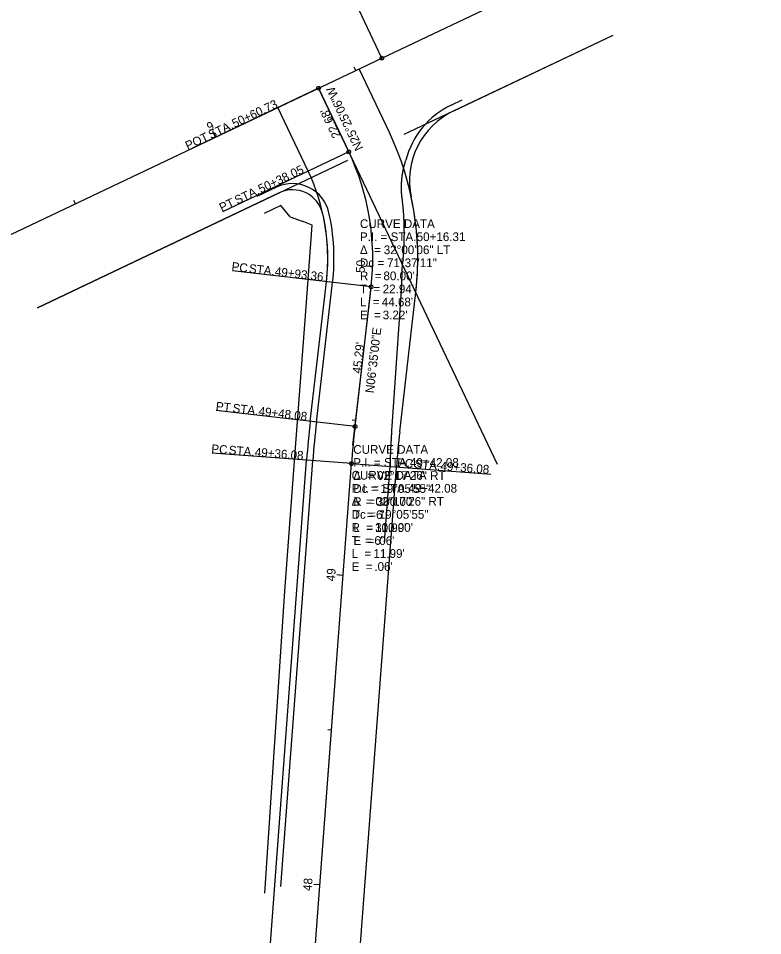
# Model space of a CAD drawing. Extents: x 219353 to 221640, y 361458 to 364236.
# Drawn here: x 220121.2 to 220361, y 361769.6 to 362065.1 of the extents above; entities that cross this region are included whole.
import ezdxf

# ---------------------------------------------------------------- set-up
doc = ezdxf.new("R2010")
doc.units = 0
for name, color, linetype in [('DR_P_Cells', 7, 'Continuous'), ('DR_P_GenericNode', 7, 'Continuous'), ('DR_P_Storm_Sewer', 7, 'Continuous'), ('DR_X_Cells', 7, 'Continuous'), ('DR_X_Storm_Sewer', 7, 'Continuous'), ('DT_X_Contour_Major', 7, 'Continuous'), ('DT_X_Contour_Minor', 7, 'Continuous'), ('SC_ProfileRun1', 7, 'Continuous'), ('SC_ProfileRun2', 7, 'Continuous'), ('SC_ProfileRun3', 7, 'Continuous'), ('SC_Scratch1', 7, 'Continuous'), ('UT_X_Sanitary_Cells', 7, 'Continuous'), ('UT_X_Sanitary_Line', 7, 'Continuous')]:
    doc.layers.add(name, color=color, linetype=linetype)

msp = doc.modelspace()

# ---------------------------------------------------------------- linework, layer by layer
at = {"layer": 'DR_X_Cells'}
for p, q in [((220238.34, 362052.3), (220219.02, 362092.94)), ((220217.91, 362042.59), (220177.27, 362023.28)), ((220227.64, 362022.11), (220187, 362002.79)), ((220234.86, 361978.6), (220190.16, 361983.76)), ((220229.67, 361933.61), (220184.97, 361938.77)), ((220228.53, 361921.67), (220273.41, 361918.3))]:
    msp.add_line(p, q, dxfattribs=at)
for centre in [(220238.34, 362052.3), (220217.91, 362042.59), (220227.64, 362022.11), (220234.86, 361978.6), (220229.67, 361933.61), (220228.53, 361921.67)]:
    msp.add_circle(centre, 0.6, dxfattribs=at)
at = {"layer": 'DT_X_Contour_Major'}
for p, q in [((220238.34, 362052.3), (220361, 362110.59)), ((220238.34, 362052.3), (220342.97, 362102.03)), ((220238.34, 362052.3), (220342.97, 362102.03)), ((219371.89, 361640.54), (220238.34, 362052.3)), ((219371.89, 361640.54), (220238.34, 362052.3)), ((220217.91, 362042.59), (220275.47, 361921.48)), ((220217.91, 362042.59), (220227.64, 362022.11)), ((220227.64, 362022.11), (220217.91, 362042.59)), ((220229.67, 361933.61), (220234.86, 361978.6)), ((220228.98, 361927.65), (220234.72, 361977.36)), ((220203.38, 361586.53), (220228.53, 361921.67)), ((220203.38, 361586.53), (220223.37, 361852.86))]:
    msp.add_line(p, q, dxfattribs=at)
for centre, radius, start, end in [((220155.39, 361987.77), 80, 353.4167, 25.4184), ((220155.39, 361987.77), 80, 353.4167, 25.4184), ((220527.69, 361899.21), 300, 173.4167, 175.7073), ((220527.69, 361899.21), 300, 173.4167, 175.7073)]:
    msp.add_arc(centre, radius, start, end, dxfattribs=at)
at = {"layer": 'DT_X_Contour_Minor'}
for p, q in [((220249.18, 362029.49), (220312.8, 362059.72)), ((220261.51, 362035.35), (220312.8, 362059.72)), ((220261.51, 362035.35), (220312.8, 362059.72)), ((220240.74, 362028.33), (220231.01, 362048.82)), ((220214.55, 362015.88), (220204.81, 362036.37)), ((220245.5, 362027.74), (220249.18, 362029.49)), ((220127.4, 361971.9), (220227.38, 362019.41)), ((220127.4, 361971.9), (220205.26, 362008.9)), ((220205.26, 362008.9), (220127.4, 361971.9)), ((220205.75, 362004.82), (220200.36, 362002.26)), ((220208.77, 362001.19), (220205.75, 362004.82)), ((220208.77, 362001.19), (220212.63, 361999.74)), ((220215.91, 361998.51), (220212.63, 361999.74)), ((220213.89, 361972.18), (220215.91, 361998.51)), ((220215.26, 361935.27), (220220.46, 361980.26)), ((220215.26, 361935.27), (220220.46, 361980.26)), ((220215.26, 361935.27), (220220.46, 361980.26)), ((220244.07, 361931.95), (220249.26, 361976.94)), ((220244.07, 361931.95), (220249.26, 361976.94)), ((220244.07, 361931.95), (220249.26, 361976.94)), ((220210.44, 361925.41), (220213.89, 361972.18)), ((220188.92, 361587.61), (220214.07, 361922.75)), ((220188.92, 361587.61), (220214.07, 361922.75)), ((220188.92, 361587.61), (220214.07, 361922.75)), ((220207.08, 361880.55), (220210.44, 361925.41)), ((220217.83, 361585.44), (220242.99, 361920.58)), ((220217.83, 361585.44), (220242.99, 361920.58)), ((220217.83, 361585.44), (220242.99, 361920.58)), ((220200.58, 361783.34), (220207.08, 361880.55))]:
    msp.add_line(p, q, dxfattribs=at)
for centre, radius, start, end in [((220272.24, 362012.77), 25, 115.4184, 192.0775), ((220272.24, 362012.77), 25, 115.4184, 192.0775), ((220155.39, 361987.77), 94.5, 353.4167, 25.4184), ((220155.39, 361987.77), 65.5, 353.4167, 25.4184), ((220209.55, 361999.87), 10, 12.5928, 115.4184), ((220209.55, 361999.87), 10, 12.5928, 115.4184), ((220155.39, 361987.77), 94.5, 353.4167, 12.0775), ((220155.39, 361987.77), 94.5, 353.4167, 12.0775), ((220155.39, 361987.77), 65.5, 353.4167, 12.5928), ((220155.39, 361987.77), 65.5, 353.4167, 12.5928), ((220527.69, 361899.21), 314.5, 173.4167, 175.7073), ((220527.69, 361899.21), 314.5, 173.4167, 175.7073), ((220527.69, 361899.21), 314.5, 173.4167, 175.7073), ((220527.69, 361899.21), 285.5, 173.4167, 175.7073), ((220527.69, 361899.21), 285.5, 173.4167, 175.7073), ((220527.69, 361899.21), 285.5, 173.4167, 175.7073)]:
    msp.add_arc(centre, radius, start, end, dxfattribs=at)
at = {"layer": 'SC_ProfileRun2'}
for p, q in [((220238.34, 362052.3), (220219.02, 362092.94)), ((220217.91, 362042.59), (220177.27, 362023.28)), ((220217.91, 362042.59), (220177.27, 362023.28)), ((220227.64, 362022.11), (220187, 362002.79)), ((220227.64, 362022.11), (220187, 362002.79)), ((220234.86, 361978.6), (220190.16, 361983.76)), ((220234.86, 361978.6), (220190.16, 361983.76)), ((220229.67, 361933.61), (220184.97, 361938.77)), ((220229.67, 361933.61), (220184.97, 361938.77)), ((220228.53, 361921.67), (220183.66, 361925.04)), ((220228.53, 361921.67), (220273.41, 361918.3))]:
    msp.add_line(p, q, dxfattribs=at)
for centre in [(220238.34, 362052.3), (220217.91, 362042.59), (220217.91, 362042.59), (220227.64, 362022.11), (220227.64, 362022.11), (220234.86, 361978.6), (220234.86, 361978.6), (220229.67, 361933.61), (220229.67, 361933.61), (220228.53, 361921.67), (220228.53, 361921.67)]:
    msp.add_circle(centre, 0.6, dxfattribs=at)
at = {"layer": 'SC_ProfileRun3'}
for p, q in [((220184.77, 362026.84), (220184.26, 362027.93)), ((220235.35, 361985.21), (220233.35, 361985.28)), ((220235.35, 361985.21), (220233.35, 361985.28)), ((220225.83, 361885.69), (220224.63, 361885.78)), ((220225.83, 361885.69), (220224.63, 361885.78)), ((220218.35, 361785.97), (220217.15, 361786.06)), ((220218.35, 361785.97), (220217.15, 361786.06))]:
    msp.add_line(p, q, dxfattribs=at)
at = {"layer": 'UT_X_Sanitary_Cells'}
for p, q in [((220229.93, 362048.31), (220229.42, 362049.39)), ((220222.51, 362032.9), (220221.43, 362032.39)), ((220184.77, 362026.84), (220183.91, 362028.65)), ((220139.61, 362005.38), (220139.1, 362006.47)), ((220235.35, 361985.21), (220233.35, 361985.28)), ((220229.89, 361935.52), (220228.7, 361935.66)), ((220225.83, 361885.69), (220223.84, 361885.84)), ((220222.09, 361835.83), (220220.89, 361835.92)), ((220218.35, 361785.97), (220216.35, 361786.12))]:
    msp.add_line(p, q, dxfattribs=at)
at = {"layer": 'UT_X_Sanitary_Line'}
for p, q in [((220260.65, 362037.16), (220264.17, 362038.83)), ((220260.65, 362037.16), (220264.17, 362038.83)), ((220260.65, 362037.16), (220264.17, 362038.83)), ((220204.4, 362010.71), (220198.04, 362007.68)), ((220217.25, 361935.04), (220222.44, 361980.03)), ((220241.57, 361932.23), (220244.64, 361977.47)), ((220241.57, 361932.23), (220244.64, 361977.47)), ((220241.57, 361932.23), (220244.64, 361977.47)), ((220205.77, 361785.49), (220216.07, 361922.6)), ((220239.17, 361896.41), (220241, 361920.73)), ((220239.17, 361896.41), (220241, 361920.73))]:
    msp.add_line(p, q, dxfattribs=at)
for centre, radius, start, end in [((220272.24, 362012.77), 27, 115.4184, 165.8654), ((220272.24, 362012.77), 27, 115.4184, 165.8654), ((220272.24, 362012.77), 27, 115.4184, 165.8654), ((220209.55, 361999.87), 12, 12.5928, 115.4184), ((220155.39, 361987.77), 67.5, 353.4167, 12.5928), ((220527.69, 361899.21), 312.5, 173.4167, 175.7073), ((220527.69, 361899.21), 287.5, 175.6312, 175.7073), ((220527.69, 361899.21), 287.5, 175.6312, 175.7073)]:
    msp.add_arc(centre, radius, start, end, dxfattribs=at)
for points in [[(220244.88, 362006.92), (220244.85, 362007.13), (220244.8, 362007.55), (220244.74, 362008.19), (220244.69, 362008.83), (220244.65, 362009.47), (220244.63, 362010.1), (220244.63, 362010.74), (220244.64, 362011.37), (220244.66, 362012.01), (220244.7, 362012.64), (220244.75, 362013.27), (220244.82, 362013.89), (220244.9, 362014.52), (220245, 362015.14), (220245.11, 362015.75), (220245.23, 362016.37), (220245.37, 362016.98), (220245.52, 362017.58), (220245.69, 362018.18), (220245.87, 362018.78), (220246, 362019.17), (220246.06, 362019.37)], [(220244.88, 362006.92), (220244.85, 362007.13), (220244.8, 362007.55), (220244.74, 362008.19), (220244.69, 362008.83), (220244.65, 362009.47), (220244.63, 362010.1), (220244.63, 362010.74), (220244.64, 362011.37), (220244.66, 362012.01), (220244.7, 362012.64), (220244.75, 362013.27), (220244.82, 362013.89), (220244.9, 362014.52), (220245, 362015.14), (220245.11, 362015.75), (220245.23, 362016.37), (220245.37, 362016.98), (220245.52, 362017.58), (220245.69, 362018.18), (220245.87, 362018.78), (220246, 362019.17), (220246.06, 362019.37)], [(220244.88, 362006.92), (220244.85, 362007.13), (220244.8, 362007.55), (220244.74, 362008.19), (220244.69, 362008.83), (220244.65, 362009.47), (220244.63, 362010.1), (220244.63, 362010.74), (220244.64, 362011.37), (220244.66, 362012.01), (220244.7, 362012.64), (220244.75, 362013.27), (220244.82, 362013.89), (220244.9, 362014.52), (220245, 362015.14), (220245.11, 362015.75), (220245.23, 362016.37), (220245.37, 362016.98), (220245.52, 362017.58), (220245.69, 362018.18), (220245.87, 362018.78), (220246, 362019.17), (220246.06, 362019.37)], [(220244.82, 361984.32), (220244.87, 361984.69), (220244.96, 361985.43), (220245.08, 361986.55), (220245.19, 361987.67), (220245.29, 361988.79), (220245.37, 361989.91), (220245.44, 361991.04), (220245.49, 361992.16), (220245.53, 361993.29), (220245.55, 361994.42), (220245.56, 361995.56), (220245.56, 361996.69), (220245.54, 361997.82), (220245.51, 361998.96), (220245.46, 362000.1), (220245.4, 362001.23), (220245.33, 362002.37), (220245.24, 362003.51), (220245.14, 362004.64), (220245.02, 362005.78), (220244.93, 362006.54), (220244.88, 362006.92)], [(220244.82, 361984.32), (220244.87, 361984.69), (220244.96, 361985.43), (220245.08, 361986.55), (220245.19, 361987.67), (220245.29, 361988.79), (220245.37, 361989.91), (220245.44, 361991.04), (220245.49, 361992.16), (220245.53, 361993.29), (220245.55, 361994.42), (220245.56, 361995.56), (220245.56, 361996.69), (220245.54, 361997.82), (220245.51, 361998.96), (220245.46, 362000.1), (220245.4, 362001.23), (220245.33, 362002.37), (220245.24, 362003.51), (220245.14, 362004.64), (220245.02, 362005.78), (220244.93, 362006.54), (220244.88, 362006.92)], [(220244.82, 361984.32), (220244.87, 361984.69), (220244.96, 361985.43), (220245.08, 361986.55), (220245.19, 361987.67), (220245.29, 361988.79), (220245.37, 361989.91), (220245.44, 361991.04), (220245.49, 361992.16), (220245.53, 361993.29), (220245.55, 361994.42), (220245.56, 361995.56), (220245.56, 361996.69), (220245.54, 361997.82), (220245.51, 361998.96), (220245.46, 362000.1), (220245.4, 362001.23), (220245.33, 362002.37), (220245.24, 362003.51), (220245.14, 362004.64), (220245.02, 362005.78), (220244.93, 362006.54), (220244.88, 362006.92)], [(220244.64, 361977.47), (220244.64, 361977.58), (220244.66, 361977.81), (220244.68, 361978.15), (220244.7, 361978.5), (220244.72, 361978.84), (220244.73, 361979.18), (220244.75, 361979.53), (220244.76, 361979.87), (220244.77, 361980.21), (220244.78, 361980.55), (220244.79, 361980.9), (220244.8, 361981.24), (220244.81, 361981.58), (220244.82, 361981.92), (220244.82, 361982.27), (220244.82, 361982.61), (220244.83, 361982.95), (220244.83, 361983.29), (220244.83, 361983.64), (220244.83, 361983.98), (220244.82, 361984.21), (220244.82, 361984.32)], [(220244.64, 361977.47), (220244.64, 361977.58), (220244.66, 361977.81), (220244.68, 361978.15), (220244.7, 361978.5), (220244.72, 361978.84), (220244.73, 361979.18), (220244.75, 361979.53), (220244.76, 361979.87), (220244.77, 361980.21), (220244.78, 361980.55), (220244.79, 361980.9), (220244.8, 361981.24), (220244.81, 361981.58), (220244.82, 361981.92), (220244.82, 361982.27), (220244.82, 361982.61), (220244.83, 361982.95), (220244.83, 361983.29), (220244.83, 361983.64), (220244.83, 361983.98), (220244.82, 361984.21), (220244.82, 361984.32)], [(220244.64, 361977.47), (220244.64, 361977.58), (220244.66, 361977.81), (220244.68, 361978.15), (220244.7, 361978.5), (220244.72, 361978.84), (220244.73, 361979.18), (220244.75, 361979.53), (220244.76, 361979.87), (220244.77, 361980.21), (220244.78, 361980.55), (220244.79, 361980.9), (220244.8, 361981.24), (220244.81, 361981.58), (220244.82, 361981.92), (220244.82, 361982.27), (220244.82, 361982.61), (220244.83, 361982.95), (220244.83, 361983.29), (220244.83, 361983.64), (220244.83, 361983.98), (220244.82, 361984.21), (220244.82, 361984.32)], [(220241.03, 361921.11), (220241.03, 361921.3), (220241.04, 361921.67), (220241.06, 361922.23), (220241.08, 361922.78), (220241.1, 361923.34), (220241.12, 361923.89), (220241.14, 361924.45), (220241.17, 361925.01), (220241.19, 361925.56), (220241.22, 361926.12), (220241.24, 361926.67), (220241.27, 361927.23), (220241.3, 361927.79), (220241.33, 361928.34), (220241.36, 361928.9), (220241.39, 361929.45), (220241.43, 361930.01), (220241.46, 361930.57), (220241.49, 361931.12), (220241.53, 361931.68), (220241.56, 361932.05), (220241.57, 361932.23)], [(220241.03, 361921.11), (220241.03, 361921.3), (220241.04, 361921.67), (220241.06, 361922.23), (220241.08, 361922.78), (220241.1, 361923.34), (220241.12, 361923.89), (220241.14, 361924.45), (220241.17, 361925.01), (220241.19, 361925.56), (220241.22, 361926.12), (220241.24, 361926.67), (220241.27, 361927.23), (220241.3, 361927.79), (220241.33, 361928.34), (220241.36, 361928.9), (220241.39, 361929.45), (220241.43, 361930.01), (220241.46, 361930.57), (220241.49, 361931.12), (220241.53, 361931.68), (220241.56, 361932.05), (220241.57, 361932.23)], [(220241.03, 361921.11), (220241.03, 361921.3), (220241.04, 361921.67), (220241.06, 361922.23), (220241.08, 361922.78), (220241.1, 361923.34), (220241.12, 361923.89), (220241.14, 361924.45), (220241.17, 361925.01), (220241.19, 361925.56), (220241.22, 361926.12), (220241.24, 361926.67), (220241.27, 361927.23), (220241.3, 361927.79), (220241.33, 361928.34), (220241.36, 361928.9), (220241.39, 361929.45), (220241.43, 361930.01), (220241.46, 361930.57), (220241.49, 361931.12), (220241.53, 361931.68), (220241.56, 361932.05), (220241.57, 361932.23)]]:
    msp.add_open_spline(points, degree=3, dxfattribs=at)

# ---------------------------------------------------------------- texts
at = {"layer": 'DR_P_Cells'}
for s, rotation, p in [("22.68'", 115.4184, (220225.13, 362027.31)), ("45.29'", 83.4167, (220231.59, 361950.58))]:
    msp.add_text(s, height=2.8, rotation=rotation, dxfattribs=at).set_placement(p)
at = {"layer": 'DR_P_GenericNode'}
for s, rotation, p in [("22.68'", 115.4184, (220225.13, 362027.31)), ("22.68'", 115.4184, (220225.13, 362027.31)), ("45.29'", 83.4167, (220231.59, 361950.58)), ("45.29'", 83.4167, (220231.59, 361950.58))]:
    msp.add_text(s, height=2.8, rotation=rotation, dxfattribs=at).set_placement(p)
at = {"layer": 'DR_P_Storm_Sewer'}
for s, p in [('CURVE DATA', (220231.25, 361997.55)), ('P.I. = STA. ', (220231.25, 361993.35)), ('50+16.31', (220249.52, 361993.35)), ('Δ  = ', (220231.25, 361989.15)), ('32°00\'06" LT', (220238.93, 361989.15)), ('Dc = ', (220231.25, 361984.95)), ('71°37\'11"', (220239.99, 361984.95)), ('R  = ', (220231.25, 361980.75)), ("80.00'", (220238.83, 361980.75)), ('T  = ', (220231.25, 361976.55)), ("22.94'", (220238.59, 361976.55)), ('L  = ', (220231.25, 361972.35)), ("44.68'", (220238.29, 361972.35)), ('E  = ', (220231.25, 361968.15)), ("3.22'", (220238.59, 361968.15)), ('CURVE DATA', (220229.1, 361924.84)), ('P.I. = STA. ', (220229.1, 361920.64)), ('49+42.08', (220247.37, 361920.64)), ('Δ  = ', (220229.1, 361916.44)), ('02°17\'26" RT', (220236.78, 361916.44)), ('Dc = ', (220229.1, 361912.24)), ('19°05\'55"', (220237.84, 361912.24)), ('R  = ', (220229.1, 361908.04)), ("300.00'", (220236.68, 361908.04)), ('T  = ', (220229.1, 361903.84)), ("6'", (220236.44, 361903.84)), ('L  = ', (220229.1, 361899.64)), ("11.99'", (220236.14, 361899.64)), ('E  = ', (220229.1, 361895.44)), (".06'", (220236.44, 361895.44))]:
    msp.add_text(s, height=2.8, dxfattribs=at).set_placement(p)
at = {"layer": 'DR_X_Cells'}
for s, rotation, p in [('50+60.73', 25.4184, (220190.84, 362029.77)), (' STA. ', 25.4184, (220182.3, 362025.72)), ('POT', 25.4184, (220175.8, 362022.63)), ('50+38.05', 25.4184, (220199.28, 362008.68)), (' STA. ', 25.4184, (220190.75, 362004.62)), ('PT', 25.4184, (220186.76, 362002.72)), ('PC', 353.4167, (220189.78, 361983.84)), (' STA. ', 353.4167, (220194.33, 361983.32)), ('49+93.36', 353.4167, (220203.72, 361982.23)), ('PT', 353.4167, (220184.7, 361938.84)), (' STA. ', 353.4167, (220189.08, 361938.33)), ('49+48.08', 353.4167, (220198.47, 361937.25)), ('PC', 355.7073, (220243.13, 361920.62)), (' STA. ', 355.7073, (220247.7, 361920.27)), ('49+36.08', 355.7073, (220257.13, 361919.56))]:
    msp.add_text(s, height=2.8, rotation=rotation, dxfattribs=at).set_placement(p)
at = {"layer": 'DR_X_Storm_Sewer'}
for s, p in [('CURVE DATA', (220231.25, 361997.55)), ('P.I. = STA. ', (220231.25, 361993.35)), ('50+16.31', (220249.52, 361993.35)), ('Δ  = ', (220231.25, 361989.15)), ('32°00\'06" LT', (220238.93, 361989.15)), ('Dc = ', (220231.25, 361984.95)), ('71°37\'11"', (220239.99, 361984.95)), ('R  = ', (220231.25, 361980.75)), ("80.00'", (220238.83, 361980.75)), ('T  = ', (220231.25, 361976.55)), ("22.94'", (220238.59, 361976.55)), ('L  = ', (220231.25, 361972.35)), ("44.68'", (220238.29, 361972.35)), ('E  = ', (220231.25, 361968.15)), ("3.22'", (220238.59, 361968.15)), ('CURVE DATA', (220228.56, 361916.52)), ('P.I. = STA. ', (220228.56, 361912.32)), ('49+42.08', (220246.83, 361912.32)), ('Δ  = ', (220228.56, 361908.12)), ('02°17\'26" RT', (220236.24, 361908.12)), ('Dc = ', (220228.56, 361903.92)), ('19°05\'55"', (220237.3, 361903.92)), ('R  = ', (220228.56, 361899.72)), ("300.00'", (220236.15, 361899.72)), ('T  = ', (220228.56, 361895.52)), ("6'", (220235.9, 361895.52)), ('L  = ', (220228.56, 361891.32)), ("11.99'", (220235.6, 361891.32)), (".06'", (220235.9, 361887.12)), ('E  = ', (220228.56, 361887.12))]:
    msp.add_text(s, height=2.8, dxfattribs=at).set_placement(p)
at = {"layer": 'SC_ProfileRun1'}
for s, rotation, p in [('N25°25\'06"W', 115.4184, (220232.4, 362023.29)), ('N25°25\'06"W', 115.4184, (220232.4, 362023.29)), ('N06°35\'00"E', 83.4167, (220235.73, 361944.26)), ('N06°35\'00"E', 83.4167, (220235.73, 361944.26))]:
    msp.add_text(s, height=2.8, rotation=rotation, dxfattribs=at).set_placement(p)
at = {"layer": 'SC_ProfileRun2'}
for s, rotation, p in [('50+60.73', 25.4184, (220190.84, 362029.77)), ('50+60.73', 25.4184, (220190.84, 362029.77)), (' STA. ', 25.4184, (220182.3, 362025.72)), (' STA. ', 25.4184, (220182.3, 362025.72)), ('POT', 25.4184, (220175.8, 362022.63)), ('POT', 25.4184, (220175.8, 362022.63)), ('50+38.05', 25.4184, (220199.28, 362008.68)), ('50+38.05', 25.4184, (220199.28, 362008.68)), (' STA. ', 25.4184, (220190.75, 362004.62)), (' STA. ', 25.4184, (220190.75, 362004.62)), ('PT', 25.4184, (220186.76, 362002.72)), ('PT', 25.4184, (220186.76, 362002.72)), ('PC', 353.4167, (220189.78, 361983.84)), ('PC', 353.4167, (220189.78, 361983.84)), (' STA. ', 353.4167, (220194.33, 361983.32)), (' STA. ', 353.4167, (220194.33, 361983.32)), ('49+93.36', 353.4167, (220203.72, 361982.23)), ('49+93.36', 353.4167, (220203.72, 361982.23)), ('PT', 353.4167, (220184.7, 361938.84)), ('PT', 353.4167, (220184.7, 361938.84)), (' STA. ', 353.4167, (220189.08, 361938.33)), (' STA. ', 353.4167, (220189.08, 361938.33)), ('49+48.08', 353.4167, (220198.47, 361937.25)), ('49+48.08', 353.4167, (220198.47, 361937.25)), ('PC', 355.7073, (220183.3, 361925.11)), (' STA. ', 355.7073, (220187.87, 361924.76)), ('49+36.08', 355.7073, (220197.3, 361924.06)), ('PC', 355.7073, (220243.13, 361920.62)), (' STA. ', 355.7073, (220247.7, 361920.27)), ('49+36.08', 355.7073, (220257.13, 361919.56))]:
    msp.add_text(s, height=2.8, rotation=rotation, dxfattribs=at).set_placement(p)
at = {"layer": 'SC_ProfileRun3'}
msp.add_text('50', height=2.8, rotation=88.1689, dxfattribs=at).set_placement((220232.78, 361983.06))
msp.add_text('50', height=2.8, rotation=88.1689, dxfattribs=at).set_placement((220232.78, 361983.06))
at = {"layer": 'SC_Scratch1'}
for s, rotation, p in [('N25°25\'06"W', 115.4184, (220232.4, 362023.29)), ('N06°35\'00"E', 83.4167, (220235.73, 361944.26))]:
    msp.add_text(s, height=2.8, rotation=rotation, dxfattribs=at).set_placement(p)
at = {"layer": 'UT_X_Sanitary_Cells'}
for s, rotation, p in [('9', 25.4184, (220182.72, 362028.64)), ('50', 88.1689, (220232.78, 361983.06)), ('49', 85.7073, (220223.17, 361883.68)), ('48', 85.7073, (220215.69, 361783.94))]:
    msp.add_text(s, height=2.8, rotation=rotation, dxfattribs=at).set_placement(p)

doc.saveas('drawing.dxf')
